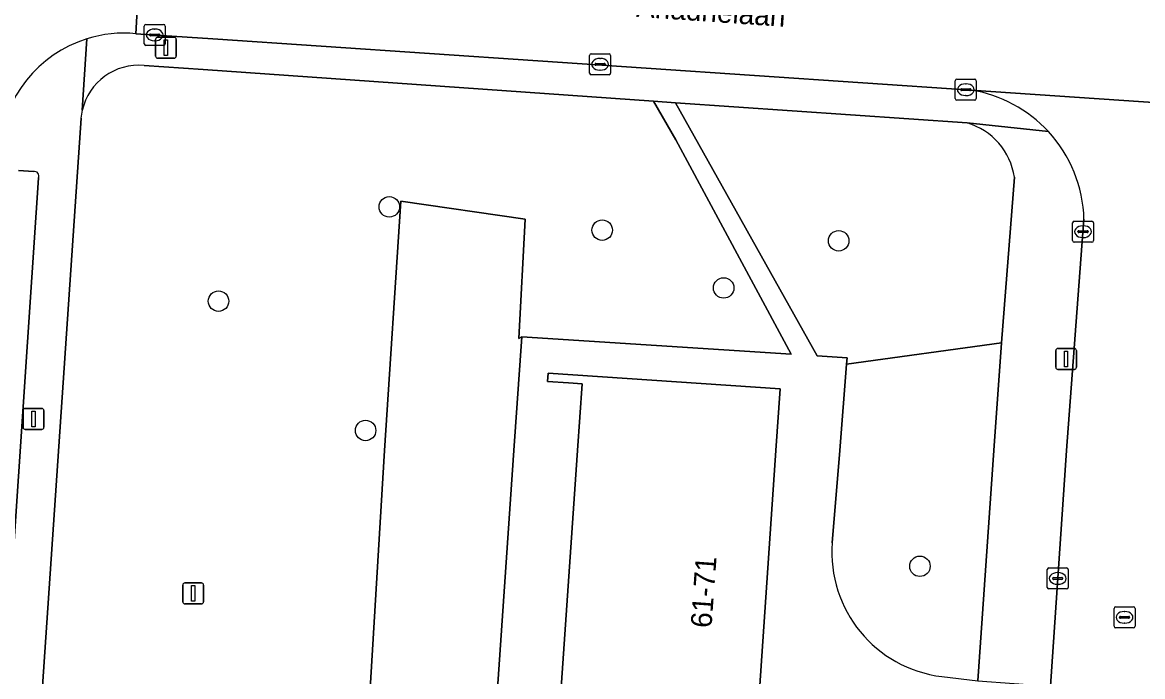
# Model space of a CAD drawing. Extents: x 161848 to 162726, y 385382 to 386521.
# Drawn here: x 162009.2 to 162062.7, y 385489.2 to 385520.5 of the extents above; entities that cross this region are included whole.
import ezdxf

# ---------------------------------------------------------------- set-up
doc = ezdxf.new("R2010")
doc.units = 0
for name, color, linetype in [('IMGEO_Boom', 7, 'Continuous'), ('IMGEO_Groenvoorziening', 7, 'Continuous'), ('IMGEO_Kolk', 7, 'Continuous'), ('IMGEO_Lichtmast', 7, 'Continuous'), ('IMGEO_Openbare_ruimte_label', 7, 'Continuous'), ('IMGEO_Pand', 7, 'Continuous'), ('IMGEO_Pand_nummerreeks', 7, 'Continuous'), ('IMGEO_Parkeervlak_open', 7, 'Continuous'), ('IMGEO_Rijbaan_lokaal_open', 7, 'Continuous'), ('IMGEO_Rioolput', 7, 'Continuous'), ('IMGEO_Verkeersbordpaal', 7, 'Continuous'), ('IMGEO_Voetpad_open', 7, 'Continuous')]:
    doc.layers.add(name, color=color, linetype=linetype)

msp = doc.modelspace()

# ---------------------------------------------------------------- linework, layer by layer
at = {"layer": 'IMGEO_Boom'}
for centre in [(162026.734, 385511.644), (162036.904, 385510.535), (162048.203, 385510.025), (162042.708, 385507.772), (162018.575, 385507.142), (162025.601, 385500.964), (162052.085, 385494.475)]:
    msp.add_circle(centre, 0.489, dxfattribs=at)
at = {"layer": 'IMGEO_Groenvoorziening'}
for points in [[(162030.286, 385464.925), (162024.414, 385465.355), (162026.511, 385500), (162027.29, 385511.911), (162033.22, 385511.065), (162032.92, 385505.364), (162033.063, 385505.43), (162045.927, 385504.602), (162040.416, 385514.855), (162039.361, 385516.687), (162017.833, 385518.201), (162015.015, 385518.403)], [(162054.346, 385515.652), (162040.412, 385516.614), (162047.183, 385504.522), (162048.608, 385504.43), (162048.584, 385504.131), (162055.981, 385505.157), (162056.598, 385513.06)], [(162012.004, 385515.889), (162010.031, 385486.872), (162010.886, 385486.823), (162010.76, 385484.131), (162009.85, 385484.211), (162007.414, 385448.376), (162005.771, 385422.427), (162005.023, 385411.442), (162005.334, 385404.615), (162006.907, 385403.783)], [(162053.133, 385489.205), (162054.849, 385488.996), (162055.62, 385500), (162055.981, 385505.157), (162048.584, 385504.131), (162048.252, 385500), (162047.899, 385495.599)]]:
    msp.add_lwpolyline(points, dxfattribs=at)
msp.add_lwpolyline([(162033.063, 385505.43), (162032.92, 385505.364), (162033.22, 385511.065), (162027.29, 385511.911), (162026.511, 385500), (162024.414, 385465.355), (162030.286, 385464.925), (162032.691, 385500)], close=True, dxfattribs=at)
for centre, radius, start, end in [((162014.769, 385515.638), 2.776, 84.9127, 167.1189), ((162014.637, 385515.656), 2.644, 166.8492, 174.9338), ((162053.458, 385512.607), 3.172, 8.2189, 73.7511), ((162053.854, 385495.135), 5.973, 175.5405, 263.0656)]:
    msp.add_arc(centre, radius, start, end, dxfattribs=at)
at = {"layer": 'IMGEO_Kolk'}
for p, q in [((162015.023, 385519.433), (162015.023, 385520.285)), ((162015.098, 385520.359), (162015.95, 385520.359)), ((162016.024, 385520.285), (162016.024, 385519.433)), ((162015.282, 385519.853), (162015.282, 385519.865)), ((162015.72, 385519.816), (162015.322, 385519.816)), ((162015.325, 385519.902), (162015.723, 385519.902)), ((162015.511, 385520.139), (162015.536, 385520.139)), ((162015.766, 385519.865), (162015.766, 385519.853)), ((162015.95, 385519.359), (162015.098, 385519.359)), ((162015.534, 385519.579), (162015.509, 385519.579)), ((162036.303, 385518.03), (162036.303, 385518.882)), ((162036.378, 385518.956), (162037.23, 385518.956)), ((162036.791, 385518.736), (162036.816, 385518.736)), ((162037.304, 385518.882), (162037.304, 385518.03)), ((162036.562, 385518.45), (162036.562, 385518.462)), ((162037, 385518.413), (162036.602, 385518.413)), ((162036.605, 385518.499), (162037.003, 385518.499)), ((162036.814, 385518.176), (162036.789, 385518.176)), ((162037.046, 385518.462), (162037.046, 385518.45)), ((162037.23, 385517.956), (162036.378, 385517.956)), ((162053.775, 385516.818), (162053.775, 385517.67)), ((162053.85, 385517.744), (162054.702, 385517.744)), ((162054.776, 385517.67), (162054.776, 385516.818)), ((162054.034, 385517.238), (162054.034, 385517.25)), ((162054.472, 385517.201), (162054.074, 385517.201)), ((162054.077, 385517.287), (162054.475, 385517.287)), ((162054.263, 385517.524), (162054.288, 385517.524)), ((162054.518, 385517.25), (162054.518, 385517.238)), ((162054.702, 385516.744), (162053.85, 385516.744)), ((162054.286, 385516.964), (162054.261, 385516.964)), ((162059.376, 385510.034), (162059.376, 385510.886)), ((162059.451, 385510.96), (162060.303, 385510.96)), ((162059.864, 385510.74), (162059.889, 385510.74)), ((162060.377, 385510.886), (162060.377, 385510.034)), ((162059.635, 385510.454), (162059.635, 385510.466)), ((162060.073, 385510.417), (162059.675, 385510.417)), ((162059.678, 385510.503), (162060.076, 385510.503)), ((162059.887, 385510.18), (162059.862, 385510.18)), ((162060.119, 385510.466), (162060.119, 385510.454)), ((162060.303, 385509.96), (162059.451, 385509.96)), ((162058.167, 385493.467), (162058.167, 385494.319)), ((162058.242, 385494.393), (162059.094, 385494.393)), ((162058.655, 385494.173), (162058.68, 385494.173)), ((162059.168, 385494.319), (162059.168, 385493.467)), ((162058.426, 385493.887), (162058.426, 385493.899)), ((162058.864, 385493.85), (162058.466, 385493.85)), ((162058.469, 385493.936), (162058.867, 385493.936)), ((162058.678, 385493.613), (162058.653, 385493.613)), ((162058.91, 385493.899), (162058.91, 385493.887)), ((162059.094, 385493.393), (162058.242, 385493.393))]:
    msp.add_line(p, q, dxfattribs=at)
for points in [[(162015.023, 385519.433), (162015.023, 385520.285)], [(162015.098, 385520.359), (162015.95, 385520.359)], [(162016.024, 385520.285), (162016.024, 385519.433)], [(162015.95, 385519.359), (162015.098, 385519.359)], [(162036.303, 385518.03), (162036.303, 385518.882)], [(162036.378, 385518.956), (162037.23, 385518.956)], [(162037.304, 385518.882), (162037.304, 385518.03)], [(162037.23, 385517.956), (162036.378, 385517.956)], [(162053.775, 385516.818), (162053.775, 385517.67)], [(162053.85, 385517.744), (162054.702, 385517.744)], [(162054.776, 385517.67), (162054.776, 385516.818)], [(162054.702, 385516.744), (162053.85, 385516.744)], [(162059.376, 385510.034), (162059.376, 385510.886)], [(162059.451, 385510.96), (162060.303, 385510.96)], [(162060.377, 385510.886), (162060.377, 385510.034)], [(162060.303, 385509.96), (162059.451, 385509.96)], [(162058.167, 385493.467), (162058.167, 385494.319)], [(162058.242, 385494.393), (162059.094, 385494.393)], [(162059.168, 385494.319), (162059.168, 385493.467)], [(162059.094, 385493.393), (162058.242, 385493.393)]]:
    msp.add_lwpolyline(points, dxfattribs=at)
for centre, radius, start, end in [((162015.1, 385520.283), 0.0765, 91.552, 178.448), ((162015.1, 385520.283), 0.0765, 91.552, 178.448), ((162015.948, 385520.283), 0.0765, 1.552, 88.448), ((162015.948, 385520.283), 0.0765, 1.552, 88.448), ((162015.322, 385519.862), 0.0403, 85.8775, 175.7526), ((162015.319, 385519.852), 0.0366, 178.938, 274.7102), ((162015.723, 385519.859), 0.043, 264.8664, 352.4533), ((162015.727, 385519.864), 0.0386, 1.7309, 96.639), ((162015.1, 385519.435), 0.0765, 181.552, 268.448), ((162015.1, 385519.435), 0.0765, 181.552, 268.448), ((162015.948, 385519.435), 0.0765, 271.552, 358.448), ((162015.948, 385519.435), 0.0765, 271.552, 358.448), ((162036.38, 385518.88), 0.0765, 91.552, 178.448), ((162036.38, 385518.88), 0.0765, 91.552, 178.448), ((162037.228, 385518.88), 0.0765, 1.552, 88.448), ((162037.228, 385518.88), 0.0765, 1.552, 88.448), ((162036.602, 385518.459), 0.0403, 85.8775, 175.7526), ((162036.599, 385518.449), 0.0366, 178.938, 274.7102), ((162037.003, 385518.456), 0.043, 264.8664, 352.4533), ((162037.007, 385518.461), 0.0386, 1.7309, 96.639), ((162036.38, 385518.032), 0.0765, 181.552, 268.448), ((162036.38, 385518.032), 0.0765, 181.552, 268.448), ((162037.228, 385518.032), 0.0765, 271.552, 358.448), ((162037.228, 385518.032), 0.0765, 271.552, 358.448), ((162053.852, 385517.668), 0.0765, 91.552, 178.448), ((162053.852, 385517.668), 0.0765, 91.552, 178.448), ((162054.7, 385517.668), 0.0765, 1.552, 88.448), ((162054.7, 385517.668), 0.0765, 1.552, 88.448), ((162054.074, 385517.247), 0.0403, 85.8775, 175.7526), ((162054.071, 385517.237), 0.0366, 178.938, 274.7102), ((162054.475, 385517.244), 0.043, 264.8664, 352.4533), ((162054.479, 385517.249), 0.0386, 1.7309, 96.639), ((162053.852, 385516.82), 0.0765, 181.552, 268.448), ((162053.852, 385516.82), 0.0765, 181.552, 268.448), ((162054.7, 385516.82), 0.0765, 271.552, 358.448), ((162054.7, 385516.82), 0.0765, 271.552, 358.448), ((162059.453, 385510.884), 0.0765, 91.552, 178.448), ((162059.453, 385510.884), 0.0765, 91.552, 178.448), ((162060.301, 385510.884), 0.0765, 1.552, 88.448), ((162060.301, 385510.884), 0.0765, 1.552, 88.448), ((162059.453, 385510.036), 0.0765, 181.552, 268.448), ((162059.453, 385510.036), 0.0765, 181.552, 268.448), ((162059.675, 385510.463), 0.0403, 85.8775, 175.7526), ((162059.672, 385510.453), 0.0366, 178.938, 274.7102), ((162060.076, 385510.46), 0.043, 264.8664, 352.4533), ((162060.08, 385510.465), 0.0386, 1.7309, 96.639), ((162060.301, 385510.036), 0.0765, 271.552, 358.448), ((162060.301, 385510.036), 0.0765, 271.552, 358.448), ((162058.244, 385494.317), 0.0765, 91.552, 178.448), ((162058.244, 385494.317), 0.0765, 91.552, 178.448), ((162059.092, 385494.317), 0.0765, 1.552, 88.448), ((162059.092, 385494.317), 0.0765, 1.552, 88.448), ((162058.244, 385493.469), 0.0765, 181.552, 268.448), ((162058.244, 385493.469), 0.0765, 181.552, 268.448), ((162058.466, 385493.896), 0.0403, 85.8775, 175.7526), ((162058.463, 385493.886), 0.0366, 178.938, 274.7102), ((162058.867, 385493.893), 0.043, 264.8664, 352.4533), ((162058.871, 385493.898), 0.0386, 1.7309, 96.639), ((162059.092, 385493.469), 0.0765, 271.552, 358.448), ((162059.092, 385493.469), 0.0765, 271.552, 358.448)]:
    msp.add_arc(centre, radius, start, end, dxfattribs=at)
for centre, major_axis, ratio, start_param, end_param in [((162015.51, 385519.859), (-0.387, 0.002), 0.722429, 4.712389, 7.853982), ((162015.535, 385519.859), (-0.39, 0.002), 0.717154, 1.570796, 4.712389), ((162036.79, 385518.456), (-0.387, 0.002), 0.722429, 4.712389, 7.853982), ((162036.815, 385518.456), (-0.39, 0.002), 0.717154, 1.570796, 4.712389), ((162054.262, 385517.244), (-0.387, 0.002), 0.722429, 4.712389, 7.853982), ((162054.287, 385517.244), (-0.39, 0.002), 0.717154, 1.570796, 4.712389), ((162059.863, 385510.46), (-0.387, 0.002), 0.722429, 4.712389, 7.853982), ((162059.888, 385510.46), (-0.39, 0.002), 0.717154, 1.570796, 4.712389), ((162058.654, 385493.893), (-0.387, 0.002), 0.722429, 4.712389, 7.853982), ((162058.679, 385493.893), (-0.39, 0.002), 0.717154, 1.570796, 4.712389)]:
    msp.add_ellipse(centre, major_axis=major_axis, ratio=ratio, start_param=start_param, end_param=end_param, dxfattribs=at)
at = {"layer": 'IMGEO_Lichtmast'}
for p, q in [((162015.664, 385519.748), (162016.454, 385519.748)), ((162016.454, 385519.748), (162015.664, 385519.748)), ((162015.564, 385518.848), (162015.564, 385519.648)), ((162015.564, 385519.648), (162015.564, 385518.848)), ((162016.554, 385519.648), (162016.554, 385518.848)), ((162016.554, 385518.848), (162016.554, 385519.648)), ((162016.454, 385518.748), (162015.664, 385518.748)), ((162015.664, 385518.748), (162016.454, 385518.748)), ((162058.573, 385503.981), (162058.573, 385504.781)), ((162058.573, 385504.781), (162058.573, 385503.981)), ((162058.673, 385504.881), (162059.463, 385504.881)), ((162059.463, 385504.881), (162058.673, 385504.881)), ((162059.563, 385504.781), (162059.563, 385503.981)), ((162059.563, 385503.981), (162059.563, 385504.781)), ((162059.463, 385503.881), (162058.673, 385503.881)), ((162058.673, 385503.881), (162059.463, 385503.881)), ((162009.34, 385502.017), (162010.13, 385502.017)), ((162010.13, 385502.017), (162009.34, 385502.017)), ((162009.24, 385501.117), (162009.24, 385501.917)), ((162009.24, 385501.917), (162009.24, 385501.117)), ((162010.23, 385501.917), (162010.23, 385501.117)), ((162010.23, 385501.117), (162010.23, 385501.917)), ((162010.13, 385501.017), (162009.34, 385501.017)), ((162009.34, 385501.017), (162010.13, 385501.017))]:
    msp.add_line(p, q, dxfattribs=at)
for points in [[(162015.984, 385519.623), (162016.134, 385519.623), (162016.134, 385518.873), (162015.984, 385518.873), (162015.984, 385519.623)], [(162058.993, 385504.756), (162059.143, 385504.756), (162059.143, 385504.006), (162058.993, 385504.006), (162058.993, 385504.756)], [(162009.66, 385501.892), (162009.81, 385501.892), (162009.81, 385501.142), (162009.66, 385501.142), (162009.66, 385501.892)]]:
    msp.add_lwpolyline(points, dxfattribs=at)
for centre, start, end in [((162015.664, 385519.648), 90, 180), ((162015.664, 385519.648), 90, 180), ((162016.454, 385519.648), 0, 90), ((162016.454, 385519.648), 360, 90), ((162015.664, 385518.848), 180, 270), ((162015.664, 385518.848), 180, 270), ((162016.454, 385518.848), 270, 0), ((162016.454, 385518.848), 270, 0), ((162058.673, 385504.781), 90, 180), ((162058.673, 385504.781), 90, 180), ((162059.463, 385504.781), 0, 90), ((162059.463, 385504.781), 360, 90), ((162058.673, 385503.981), 180, 270), ((162058.673, 385503.981), 180, 270), ((162059.463, 385503.981), 270, 0), ((162059.463, 385503.981), 270, 0), ((162009.34, 385501.917), 90, 180), ((162009.34, 385501.917), 90, 180), ((162010.13, 385501.917), 0, 90), ((162010.13, 385501.917), 360, 90), ((162009.34, 385501.117), 180, 270), ((162009.34, 385501.117), 180, 270), ((162010.13, 385501.117), 270, 0), ((162010.13, 385501.117), 270, 0)]:
    msp.add_arc(centre, 0.1, start, end, dxfattribs=at)
at = {"layer": 'IMGEO_Pand'}
msp.add_lwpolyline([(162035.293, 385503.231), (162035.942, 385503.186), (162035.724, 385500), (162034.711, 385485.219), (162044.145, 385484.574), (162045.199, 385500), (162045.4, 385502.945), (162034.323, 385503.702), (162034.295, 385503.3)], close=True, dxfattribs=at)
at = {"layer": 'IMGEO_Parkeervlak_open'}
for points in [[(162009.727, 385513.331), (162009.019, 385513.387)], [(162004.648, 385429.041), (162006.576, 385462.653), (162009.971, 385513.026)]]:
    msp.add_lwpolyline(points, dxfattribs=at)
msp.add_arc((162009.778, 385513.121), 0.216, 333.7678, 103.5518, dxfattribs=at)
at = {"layer": 'IMGEO_Rijbaan_lokaal_open'}
for points in [[(162042.972, 385525.1), (162018.004, 385526.862), (162015.014, 385527.081), (162014.628, 385519.918), (162018.299, 385519.675), (162054.531, 385517.227), (162072.879, 385515.977)], [(162014.628, 385519.918), (162015.014, 385527.081)], [(162072.879, 385515.977), (162054.531, 385517.227)], [(162059.923, 385511.056), (162059.087, 385500), (162058.33, 385488.741), (162058.122, 385485.633), (162057.169, 385470.27), (162056.967, 385467.015), (162056.932, 385466.45)]]:
    msp.add_lwpolyline(points, dxfattribs=at)
for centre, radius, start, end in [((162014.066, 385513.969), 5.975, 107.3832, 175.3132), ((162014.065, 385513.994), 5.951, 84.5707, 107.4448), ((162053.49, 385510.876), 6.436, 42.6933, 80.6904), ((162053.493, 385510.877), 6.433, 1.5924, 42.7029)]:
    msp.add_arc(centre, radius, start, end, dxfattribs=at)
at = {"layer": 'IMGEO_Rioolput'}
for p, q in [((162061.361, 385491.61), (162061.361, 385492.462)), ((162061.436, 385492.536), (162062.288, 385492.536)), ((162062.362, 385492.462), (162062.362, 385491.61)), ((162061.62, 385492.03), (162061.62, 385492.042)), ((162062.058, 385491.993), (162061.66, 385491.993)), ((162061.663, 385492.079), (162062.061, 385492.079)), ((162061.849, 385492.316), (162061.874, 385492.316)), ((162062.104, 385492.042), (162062.104, 385492.03)), ((162062.288, 385491.536), (162061.436, 385491.536)), ((162061.872, 385491.756), (162061.847, 385491.756))]:
    msp.add_line(p, q, dxfattribs=at)
for points in [[(162061.361, 385491.61), (162061.361, 385492.462)], [(162061.436, 385492.536), (162062.288, 385492.536)], [(162062.362, 385492.462), (162062.362, 385491.61)], [(162062.288, 385491.536), (162061.436, 385491.536)]]:
    msp.add_lwpolyline(points, dxfattribs=at)
for centre, radius, start, end in [((162061.438, 385492.46), 0.0765, 91.552, 178.448), ((162061.438, 385492.46), 0.0765, 91.552, 178.448), ((162062.286, 385492.46), 0.0765, 1.552, 88.448), ((162062.286, 385492.46), 0.0765, 1.552, 88.448), ((162061.66, 385492.039), 0.0403, 85.8775, 175.7526), ((162061.657, 385492.029), 0.0366, 178.938, 274.7102), ((162062.061, 385492.036), 0.043, 264.8664, 352.4533), ((162062.065, 385492.041), 0.0386, 1.7309, 96.639), ((162061.438, 385491.612), 0.0765, 181.552, 268.448), ((162061.438, 385491.612), 0.0765, 181.552, 268.448), ((162062.286, 385491.612), 0.0765, 271.552, 358.448), ((162062.286, 385491.612), 0.0765, 271.552, 358.448)]:
    msp.add_arc(centre, radius, start, end, dxfattribs=at)
for centre, major_axis, ratio, start_param, end_param in [((162061.848, 385492.036), (-0.387, 0.002), 0.722429, 4.712389, 7.853982), ((162061.873, 385492.036), (-0.39, 0.002), 0.717154, 1.570796, 4.712389)]:
    msp.add_ellipse(centre, major_axis=major_axis, ratio=ratio, start_param=start_param, end_param=end_param, dxfattribs=at)
at = {"layer": 'IMGEO_Verkeersbordpaal'}
for p, q in [((162016.868, 385492.778), (162016.868, 385493.578)), ((162016.868, 385493.578), (162016.868, 385492.778)), ((162016.968, 385493.678), (162017.758, 385493.678)), ((162017.758, 385493.678), (162016.968, 385493.678)), ((162017.858, 385493.578), (162017.858, 385492.778)), ((162017.858, 385492.778), (162017.858, 385493.578)), ((162017.758, 385492.678), (162016.968, 385492.678)), ((162016.968, 385492.678), (162017.758, 385492.678))]:
    msp.add_line(p, q, dxfattribs=at)
msp.add_lwpolyline([(162017.288, 385493.553), (162017.438, 385493.553), (162017.438, 385492.803), (162017.288, 385492.803), (162017.288, 385493.553)], dxfattribs=at)
for centre, start, end in [((162016.968, 385493.578), 90, 180), ((162016.968, 385493.578), 90, 180), ((162017.758, 385493.578), 0, 90), ((162017.758, 385493.578), 360, 90), ((162016.968, 385492.778), 180, 270), ((162016.968, 385492.778), 180, 270), ((162017.758, 385492.778), 270, 0), ((162017.758, 385492.778), 270, 0)]:
    msp.add_arc(centre, 0.1, start, end, dxfattribs=at)
at = {"layer": 'IMGEO_Voetpad_open'}
for points in [[(162012.063, 385516.257), (162012.281, 385519.671)], [(162012.281, 385519.671), (162012.063, 385516.257)], [(162054.531, 385517.227), (162018.299, 385519.675), (162014.628, 385519.918)], [(162015.015, 385518.403), (162017.833, 385518.201), (162039.361, 385516.687), (162040.412, 385516.614), (162054.346, 385515.652), (162058.22, 385515.24)], [(162047.899, 385495.599), (162048.252, 385500), (162048.584, 385504.131), (162048.608, 385504.43), (162047.183, 385504.522), (162040.412, 385516.614), (162039.361, 385516.687), (162040.416, 385514.855), (162045.927, 385504.602), (162033.063, 385505.43), (162032.691, 385500), (162030.286, 385464.925), (162025.39, 385393.505)], [(162006.907, 385403.783), (162005.334, 385404.615), (162005.023, 385411.442), (162005.771, 385422.427), (162007.414, 385448.376), (162009.85, 385484.211), (162010.031, 385486.872), (162012.004, 385515.889)], [(162058.22, 385515.24), (162054.346, 385515.652)], [(162009.019, 385513.387), (162009.727, 385513.331)], [(162009.971, 385513.026), (162006.576, 385462.653), (162004.648, 385429.041)], [(162056.598, 385513.06), (162055.981, 385505.157), (162055.62, 385500), (162054.849, 385488.996), (162058.33, 385488.741), (162059.087, 385500), (162059.923, 385511.056)], [(162032.195, 385448.479), (162033.453, 385466.849), (162034.711, 385485.219), (162035.724, 385500), (162035.942, 385503.186), (162035.293, 385503.231), (162034.295, 385503.3), (162034.323, 385503.702), (162045.4, 385502.945), (162045.199, 385500), (162044.145, 385484.574), (162042.889, 385466.204), (162041.634, 385447.833)]]:
    msp.add_lwpolyline(points, dxfattribs=at)
for centre, radius, start, end in [((162014.066, 385513.969), 5.975, 107.3832, 175.3132), ((162014.065, 385513.994), 5.951, 84.5707, 107.4448), ((162014.769, 385515.638), 2.776, 84.9127, 167.1189), ((162053.49, 385510.876), 6.436, 42.6933, 80.6904), ((162014.637, 385515.656), 2.644, 166.8492, 174.9338), ((162053.458, 385512.607), 3.172, 8.2189, 73.7511), ((162053.493, 385510.877), 6.433, 1.5924, 42.7029), ((162009.778, 385513.121), 0.216, 333.7678, 103.5518), ((162053.854, 385495.135), 5.973, 175.5405, 263.0656)]:
    msp.add_arc(centre, radius, start, end, dxfattribs=at)

# ---------------------------------------------------------------- texts
at = {"layer": 'IMGEO_Openbare_ruimte_label'}
msp.add_text('Ariadnelaan', height=1, rotation=356.1021, dxfattribs=at).set_placement((162038.511, 385520.729))
at = {"layer": 'IMGEO_Pand_nummerreeks'}
msp.add_text('61-71', height=1, rotation=85.8342, dxfattribs=at).set_placement((162042.123, 385491.507))

doc.saveas('drawing.dxf')
